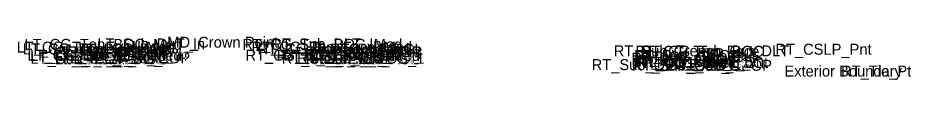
# Model space of a CAD drawing. Extents: x 0 to 6300, y 0 to 9528.
# Drawn here: x 2126 to 2207.4, y 5017.8 to 5021.8 of the extents above; entities that cross this region are included whole.
import ezdxf

# ---------------------------------------------------------------- set-up
doc = ezdxf.new("R2010")
doc.units = 0
doc.layers.add('Default', color=7, linetype='Continuous')

msp = doc.modelspace()

# ---------------------------------------------------------------- texts
at = {"layer": 'Default'}
for s, p in [('LT_CG_Top_Face_Med', (2125.866, 5020.258)), ('LT_CG_Top_Gut_Med', (2126.418, 5020.091)), ('LT_CG_Top_BOC_Med', (2126.569, 5020.508)), ('LT_PV1_PGL', (2131.503, 5020.076)), ('LT_Sub_DLT_In', (2133.217, 5020.548)), ('MD_Crown Point', (2139.582, 5020.708)), ('RT_CG_Top_BOC_Med', (2146.431, 5020.508)), ('RT_CG_Top_Face_Med', (2147.246, 5020.258)), ('RT_CG_Top_Gut_Med', (2147.8, 5020.091)), ('RT_Sub_DLT_In', (2149.068, 5020.548)), ('RT_PV1_PGL', (2154.385, 5020.076)), ('RT_Sub_Trench_Out_DLT', (2180.257, 5019.918)), ('RT_CSLP_Pnt', (2194.982, 5020.066)), ('LT_CG_Bot_BOC_Med', (2126.846, 5019.523)), ('LT_CG_Bot_IE_Med', (2127.094, 5019.493)), ('LT_Sub_IEOT_CG_1', (2127.125, 5019.243)), ('LT_PV2_OEEOP', (2129.285, 5019.826)), ('LT_PV3_OEEOP', (2129.285, 5019.576)), ('LT_Sub_OEEOP', (2129.332, 5019.201)), ('LT_PV2_IEEOP', (2130.046, 5019.826)), ('LT_Sub_IEEOP', (2130.093, 5019.201)), ('LT_CG1_Shelf_In', (2130.712, 5019.533)), ('LT_PV2_PGL', (2131.264, 5019.826)), ('LT_Sub_PGL', (2131.311, 5019.201)), ('LT_Sub_IEOP', (2133.045, 5019.288)), ('RT_CG_Bot_BOC_Med', (2146.708, 5019.523)), ('RT_CG1_Shelf_In', (2149.573, 5019.533)), ('RT_CG_Bot_IE_Med', (2149.976, 5019.493)), ('RT_Sub_IEOT_CG_1', (2150.007, 5019.243)), ('RT_Sub_IEOP', (2151.417, 5019.288)), ('RT_PV2_OEEOP', (2152.167, 5019.826)), ('RT_PV3_OEEOP', (2152.167, 5019.576)), ('RT_Sub_OEEOP', (2152.214, 5019.201)), ('RT_PV2_IEEOP', (2152.928, 5019.826)), ('RT_Sub_IEEOP', (2152.975, 5019.201)), ('RT_PV2_PGL', (2154.145, 5019.826)), ('RT_Sub_PGL', (2154.192, 5019.201)), ('RT_PV2_OEOT', (2181.873, 5019.246)), ('RT_PV1_OEOT', (2182.112, 5019.496)), ('RT_CG_Top_Face', (2182.225, 5019.876)), ('RT_CG_Top_BOC', (2182.694, 5019.876)), ('RT_CG_Top_Gut', (2182.752, 5019.376)), ('RT_Sub_OEOT_CG_1', (2178.247, 5018.663)), ('RT_PV3_OEOT', (2181.873, 5018.996)), ('RT_Sub_OEOT', (2181.92, 5018.621)), ('RT_CG_Bot_IE', (2182.221, 5018.913)), ('RT_CG1_Shelf_Out', (2182.36, 5018.853)), ('RT_CG_Bot_BOC', (2182.97, 5018.863)), ('RT_Sub_OEOP', (2185.166, 5018.598)), ('Exterior Boundary', (2195.809, 5018.073)), ('RT_Tie_Pt', (2200.972, 5018.073))]:
    msp.add_text(s, height=1, dxfattribs=at).set_placement(p)

doc.saveas('drawing.dxf')
